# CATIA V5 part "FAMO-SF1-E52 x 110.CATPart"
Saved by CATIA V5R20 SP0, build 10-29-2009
Part number: FAMO-SF1-E52 x 110
Definition: NONE
Nomenclature: FAMO-SF1-E52 x 110
Source: Unknown
Description: FAMO-SF1-E52 x 110
Bounding box of the stored display mesh (mm): x -75 to 35, y -39.5 to 39.5, z -39.5 to 39.5
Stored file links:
  C:\Users\Utente\Desktop\IO LAVORO\3D X SITO CF\X SITO\FAMO\FAMO-SF1-E52 x 110.CATPart
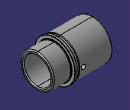
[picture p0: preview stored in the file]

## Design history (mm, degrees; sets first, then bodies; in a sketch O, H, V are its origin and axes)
Body1 "FAMO-SF1-E52 x 110" (main body)
  Solid1: solid without history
